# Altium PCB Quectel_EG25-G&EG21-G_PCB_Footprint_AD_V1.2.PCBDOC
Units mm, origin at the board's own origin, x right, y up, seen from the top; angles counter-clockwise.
Board outline 152.4 x 101.6 mm, 2 copper layers (Top Layer, Bottom Layer); 1 components, 0 nets, 132 pads, 0 vias.
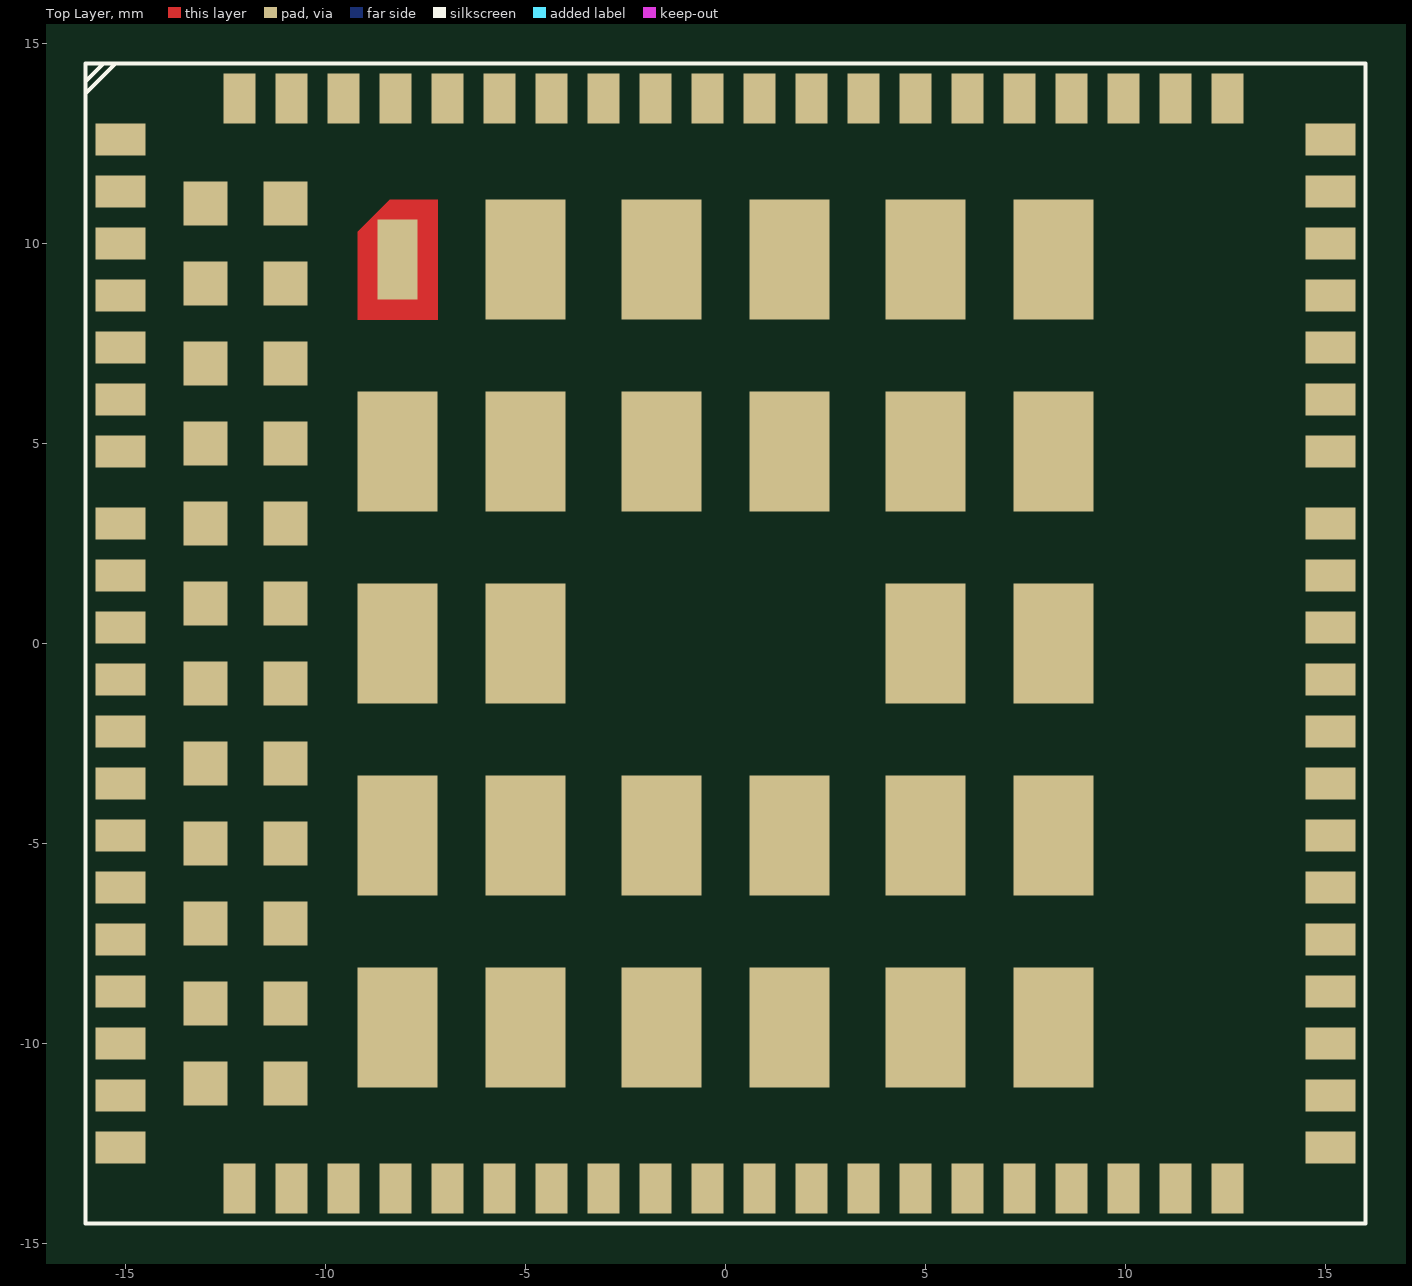
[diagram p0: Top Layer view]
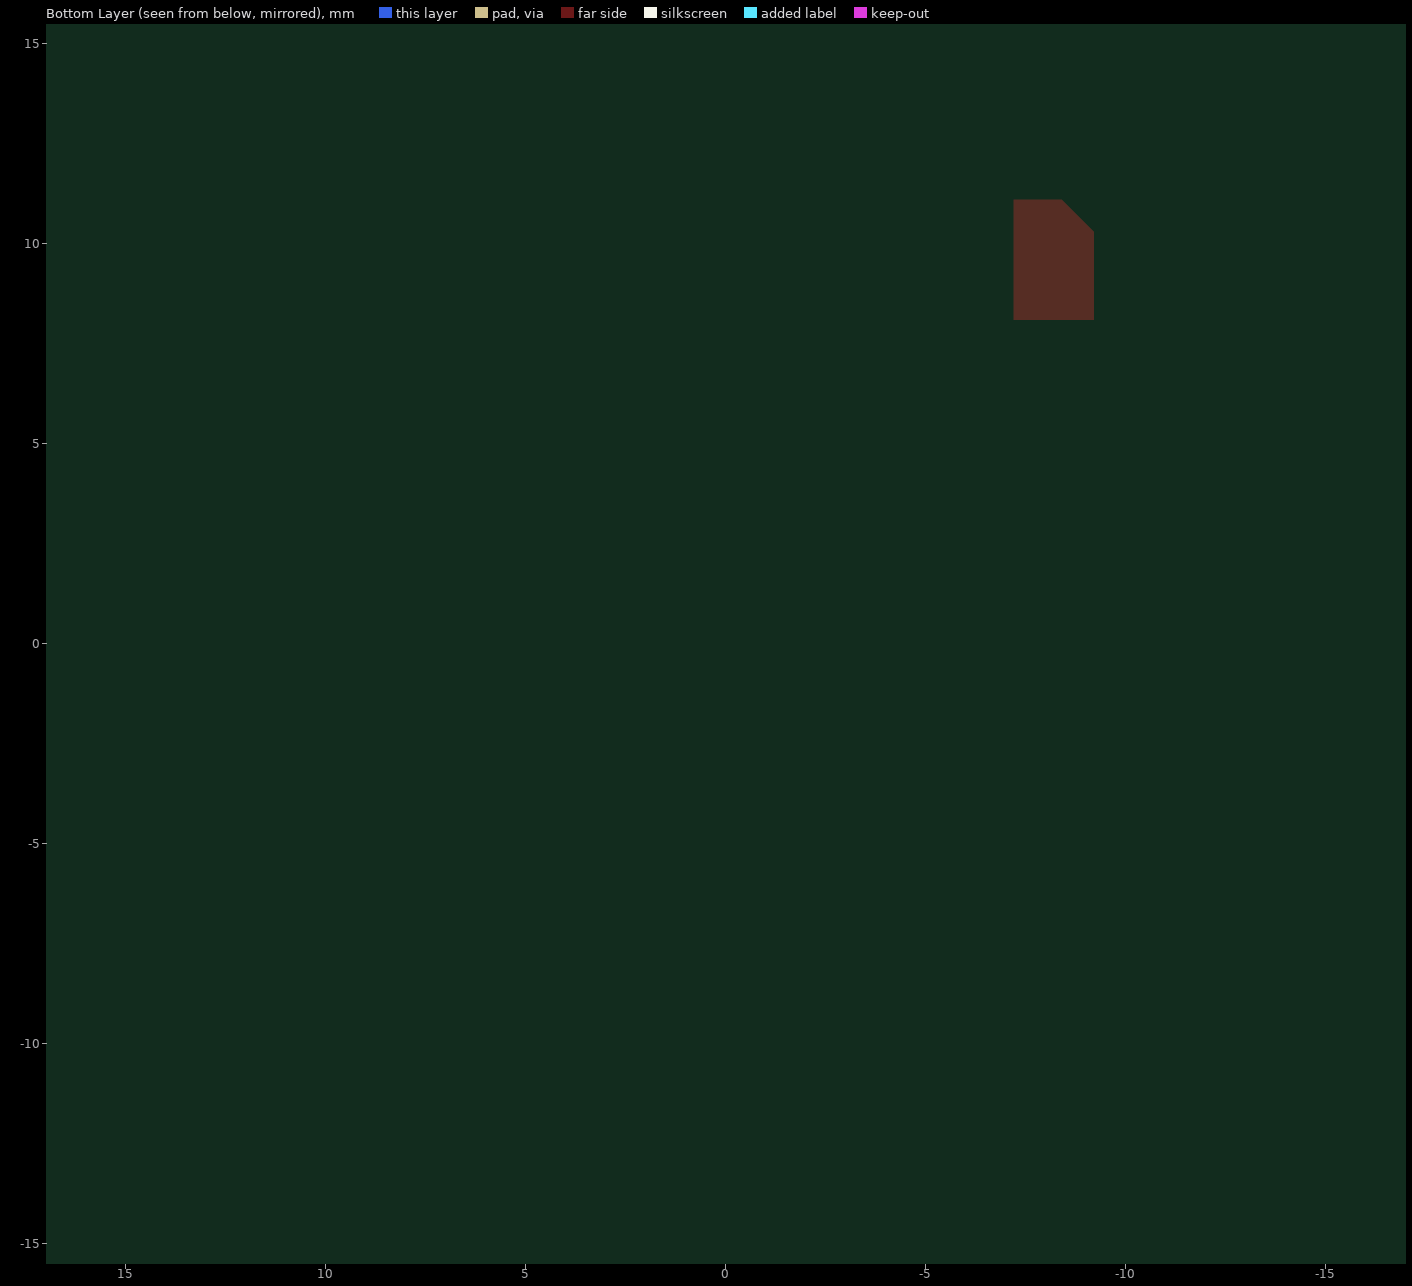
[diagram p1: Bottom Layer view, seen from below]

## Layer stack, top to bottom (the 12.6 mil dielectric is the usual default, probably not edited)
Top Layer: signal copper 0.0356
Dielectric: dielectric 0.32, FR-4, Dk 4.8
Bottom Layer: signal copper 0.0356

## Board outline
-50.673,-53.975 101.727,-53.975 101.727,47.625 -50.673,47.625

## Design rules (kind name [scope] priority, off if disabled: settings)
Clearance [All] p1: gap=0.254
ComponentClearance [All] p1: gap=0.254 collisioncheckmode=3 verticalgap=0.254
PolygonConnect [All] p1: connectstyle=Relief reliefconductorwidth=0.254 reliefentries=4 polygonreliefangle="90 Angle"
RoutingVias [All] p1: holewidth=0.711 width=1.27 viastyle="Through Hole" minholewidth=0.711 minwidth=1.27 maxholewidth=0.711 maxwidth=1.27
SolderMaskExpansion [All] p1: expansion=0.102
TestPointUsage FabricationTestPointUsage [All] p1: valid=0 allowmultiple=FALSE
Testpoint FabricationTestpoint [All] p1: side=3 testpointundercomponent=TRUE minsize=1.016 maxsize=2.54 preferedsize=1.524 minholesize=0 maxholesize=1.016 preferedholesize=0.813 testpointgrid=0.025 style=297 order=0123456789
Width [All] p1: maxlimit=0.254 minlimit=0.254 preferedwidth=0.254
18 further rules are at their usual default settings.

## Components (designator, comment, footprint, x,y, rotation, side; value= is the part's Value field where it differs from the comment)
? "Comment" EG25-G_EG21-G 0,0 r0 top

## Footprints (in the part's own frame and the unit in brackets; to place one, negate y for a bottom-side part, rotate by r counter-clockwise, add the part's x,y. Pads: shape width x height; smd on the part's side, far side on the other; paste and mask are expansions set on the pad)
EG25-G_EG21-G [mm] "EG25-G_EG21-G"
  rect 1.25x0.8 smd mask+0.05: 1(-15.125,12.6) 2(-15.125,11.3) 3(-15.125,10) 4(-15.125,8.7) 5(-15.125,7.4) 6(-15.125,6.1) 7(-15.125,4.8) 8(-15.125,0.4) 9(-15.125,-0.9) 10(-15.125,-2.2) 11(-15.125,-3.5) 12(-15.125,-4.8) 13(-15.125,-6.1) 14(-15.125,-7.4) 15(-15.125,-8.7) 16(-15.125,-10) 17(-15.125,-11.3) 18(-15.125,-12.6) 37(15.125,-12.6) 38(15.125,-11.3) 39(15.125,-10) 40(15.125,-8.7) 41(15.125,-7.4) 42(15.125,-6.1) 43(15.125,-4.8) 44(15.125,-3.5) 45(15.125,-2.2) 46(15.125,-0.9) 47(15.125,0.4) 48(15.125,4.8) 49(15.125,6.1) 50(15.125,7.4) 51(15.125,8.7) 52(15.125,10) 53(15.125,11.3) 54(15.125,12.6) 141(-15.125,3) 142(-15.125,1.7) 143(15.125,1.7) 144(15.125,3)
  rect 0.8x1.25 smd mask+0.05: 19(-9.55,-13.625) 20(-8.25,-13.625) 21(-6.95,-13.625) 22(-5.65,-13.625) 23(-4.35,-13.625) 24(-3.05,-13.625) 25(-1.75,-13.625) 26(-0.45,-13.625) 27(0.85,-13.625) 28(2.15,-13.625) 29(3.45,-13.625) 30(4.75,-13.625) 31(6.05,-13.625) 32(7.35,-13.625) 33(8.65,-13.625) 34(9.95,-13.625) 35(11.25,-13.625) 36(12.55,-13.625) 55(12.55,13.625) 56(11.25,13.625) 57(9.95,13.625) 58(8.65,13.625) 59(7.35,13.625) 60(6.05,13.625) 61(4.75,13.625) 62(3.45,13.625) 63(2.15,13.625) 64(0.85,13.625) 65(-0.45,13.625) 66(-1.75,13.625) 67(-3.05,13.625) 68(-4.35,13.625) 69(-5.65,13.625) 70(-6.95,13.625) 71(-8.25,13.625) 72(-9.55,13.625) 113(-10.85,13.625) 114(-12.15,13.625) 115(-10.85,-13.625) 116(-12.15,-13.625)
  rect 2x3 smd mask+0.05: 85(8.2,9.6) 86(8.2,4.8) 87(8.2,0) 88(8.2,-4.8) 89(8.2,-9.6) 90(5,9.6) 91(5,4.8) 92(5,0) 93(5,-4.8) 94(5,-9.6) 95(1.6,9.6) 96(1.6,4.8) 97(1.6,-4.8) 98(1.6,-9.6) 99(-1.6,9.6) 100(-1.6,4.8) 101(-1.6,-4.8) 102(-1.6,-9.6) 103(-5,9.6) 104(-5,4.8) 105(-5,0) 106(-5,-4.8) 107(-5,-9.6) 109(-8.2,4.8) 110(-8.2,0) 111(-8.2,-4.8) 112(-8.2,-9.6)
  rect 1x2 smd mask+0.05: 108(-8.2,9.6)
  rect 1.1x1.1 smd mask+0.05: 117(-11,11) 118(-11,9) 119(-11,7) 120(-11,5) 121(-11,3) 122(-11,1) 123(-11,-1) 124(-11,-3) 125(-11,-5) 126(-11,-7) 127(-11,-9) 128(-11,-11) 129(-13,11) 130(-13,9) 131(-13,7) 132(-13,5) 133(-13,3) 134(-13,1) 135(-13,-1) 136(-13,-3) 137(-13,-5) 138(-13,-7) 139(-13,-9) 140(-13,-11)
  Top Layer region: -9.2,10.3 -8.4,11.1 -7.2,11.1 -7.2,8.1 -9.2,8.1 -9.2,10.3
  Top Layer pour cut-out: 3.5,2.8 -3.5,2.8 -3.5,-2.8 3.5,-2.8 3.5,2.8
  silkscreen extent -16,-14.5 16,14.5

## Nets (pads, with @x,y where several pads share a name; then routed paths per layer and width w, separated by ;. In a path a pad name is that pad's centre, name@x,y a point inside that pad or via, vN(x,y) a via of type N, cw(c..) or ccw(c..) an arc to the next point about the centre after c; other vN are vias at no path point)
pads on no net: ?.1 ?.2 ?.3 ?.4 ?.5 ?.6 ?.7 ?.8 ?.9 ?.10 ?.11 ?.12 ?.13 ?.14 ?.15 ?.16 ?.17 ?.18 ?.19 ?.20 ?.21 ?.22 ?.23 ?.24 ?.25 ?.26 ?.27 ?.28 ?.29 ?.30 ?.31 ?.32 ?.33 ?.34 ?.35 ?.36 ?.37 ?.38 ?.39 ?.40 ?.41 ?.42 ?.43 ?.44 ?.45 ?.46 ?.47 ?.48 ?.49 ?.50 ?.51 ?.52 ?.53 ?.54 ?.55 ?.56 ?.57 ?.58 ?.59 ?.60 ?.61 ?.62 ?.63 ?.64 ?.65 ?.66 ?.67 ?.68 ?.69 ?.70 ?.71 ?.72 ?.85 ?.86 ?.87 ?.88 ?.89 ?.90 ?.91 ?.92 ?.93 ?.94 ?.95 ?.96 ?.97 ?.98 ?.99 ?.100 ?.101 ?.102 ?.103 ?.104 ?.105 ?.106 ?.107 ?.108 ?.109 ?.110 ?.111 ?.112 ?.113 ?.114 ?.115 ?.116 ?.117 ?.118 ?.119 ?.120 ?.121 ?.122 ?.123 ?.124 ?.125 ?.126 ?.127 ?.128 ?.129 ?.130 ?.131 ?.132 ?.133 ?.134 ?.135 ?.136 ?.137 ?.138 ?.139 ?.140 ?.141 ?.142 ?.143 ?.144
